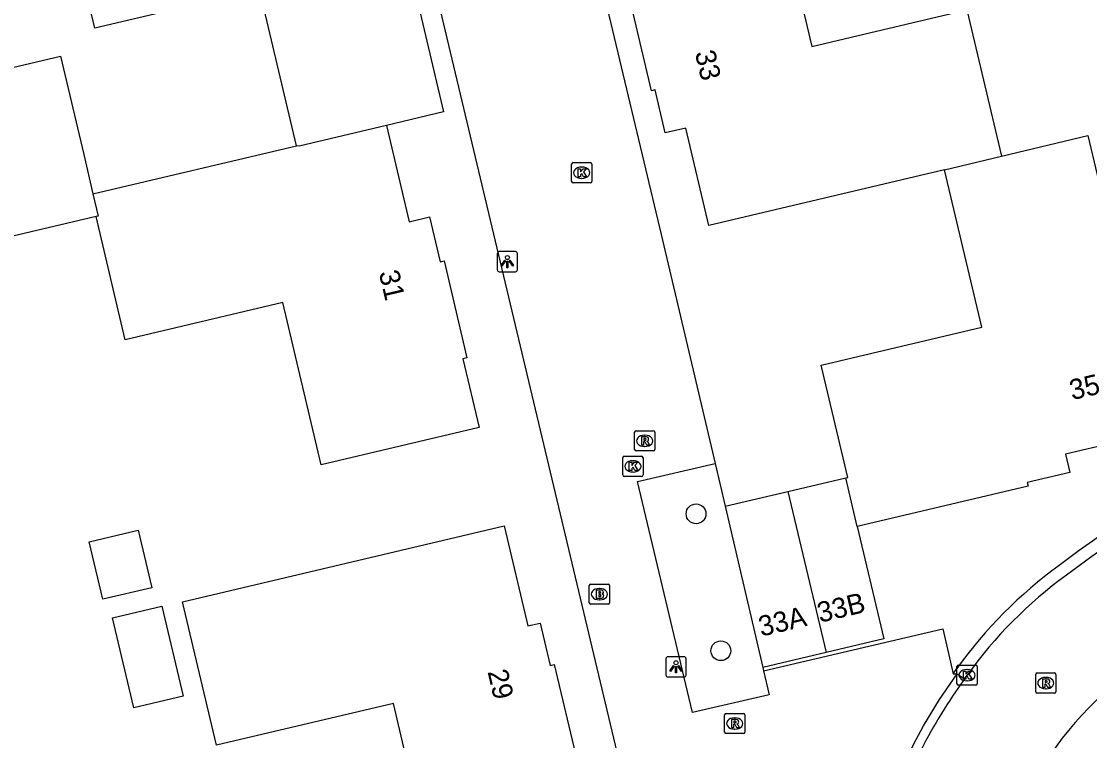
# Model space of a CAD drawing. Extents: x 157663 to 158496, y 379212 to 380934.
# Drawn here: x 158198.6 to 158251.4, y 380518.3 to 380553.9 of the extents above; entities that cross this region are included whole.
import ezdxf

# ---------------------------------------------------------------- set-up
doc = ezdxf.new("R2010")
doc.units = 0
for name, color, linetype in [('IMGEO_Boom', 7, 'Continuous'), ('IMGEO_Brandkraan', 7, 'Continuous'), ('IMGEO_Groenvoorziening', 7, 'Continuous'), ('IMGEO_Hek', 7, 'Continuous'), ('IMGEO_Kolk', 7, 'Continuous'), ('IMGEO_Lichtpunt', 7, 'Continuous'), ('IMGEO_Pand', 7, 'Continuous'), ('IMGEO_Pand_nummerreeks', 7, 'Continuous'), ('IMGEO_Rijbaan_lokaal_open', 7, 'Continuous'), ('IMGEO_Rioolput', 7, 'Continuous'), ('IMGEO_Voetpad_open', 7, 'Continuous')]:
    doc.layers.add(name, color=color, linetype=linetype)

msp = doc.modelspace()

# ---------------------------------------------------------------- linework, layer by layer
at = {"layer": 'IMGEO_Boom'}
for centre in [(158231.968, 380529.528), (158233.196, 380522.753)]:
    msp.add_circle(centre, 0.489, dxfattribs=at)
at = {"layer": 'IMGEO_Brandkraan'}
for p, q in [((158226.762, 380526.053), (158227.614, 380526.053)), ((158226.687, 380525.127), (158226.687, 380525.979)), ((158227.175, 380525.833), (158227.2, 380525.833)), ((158227.688, 380525.979), (158227.688, 380525.127)), ((158227.614, 380525.053), (158226.762, 380525.053)), ((158227.198, 380525.273), (158227.173, 380525.273))]:
    msp.add_line(p, q, dxfattribs=at)
for points in [[(158226.762, 380526.053), (158227.614, 380526.053)], [(158226.687, 380525.127), (158226.687, 380525.979)], [(158227.035, 380525.753), (158227.035, 380525.353), (158227.248, 380525.353)], [(158227.266, 380525.753), (158227.035, 380525.753)], [(158227.214, 380525.672), (158227.16, 380525.672), (158227.16, 380525.596)], [(158227.16, 380525.596), (158227.213, 380525.596)], [(158227.222, 380525.52), (158227.16, 380525.52), (158227.16, 380525.439)], [(158227.688, 380525.979), (158227.688, 380525.127)], [(158227.614, 380525.053), (158226.762, 380525.053)], [(158227.16, 380525.439), (158227.222, 380525.439)]]:
    msp.add_lwpolyline(points, dxfattribs=at)
for centre, radius, start, end in [((158226.764, 380525.977), 0.0765, 91.552, 178.448), ((158226.764, 380525.977), 0.0765, 91.552, 178.448), ((158227.612, 380525.977), 0.0765, 1.552, 88.448), ((158227.612, 380525.977), 0.0765, 1.552, 88.448), ((158227.215, 380525.634), 0.0379, 267.8285, 90.9355), ((158227.223, 380525.479), 0.0404, 269.8759, 90.5077), ((158227.27, 380525.608), 0.145, 59.4692, 91.5367), ((158227.295, 380525.655), 0.0922, 285.5137, 58.1501), ((158227.3, 380525.463), 0.105, 301.3115, 78.989), ((158226.764, 380525.129), 0.0765, 181.552, 268.448), ((158226.764, 380525.129), 0.0765, 181.552, 268.448), ((158227.254, 380525.604), 0.251, 268.6676, 293.5347), ((158227.612, 380525.129), 0.0765, 271.552, 358.448), ((158227.612, 380525.129), 0.0765, 271.552, 358.448)]:
    msp.add_arc(centre, radius, start, end, dxfattribs=at)
for centre, major_axis, ratio, start_param, end_param in [((158227.174, 380525.553), (-0.387, 0.002), 0.722429, 4.712389, 7.853982), ((158227.199, 380525.553), (-0.39, 0.002), 0.717154, 1.570796, 4.712389)]:
    msp.add_ellipse(centre, major_axis=major_axis, ratio=ratio, start_param=start_param, end_param=end_param, dxfattribs=at)
at = {"layer": 'IMGEO_Groenvoorziening'}
for points in [[(158232.907, 380532.013), (158233.403, 380529.904)], [(158235.273, 380521.928), (158235.314, 380521.754)]]:
    msp.add_lwpolyline(points, dxfattribs=at)
at = {"layer": 'IMGEO_Hek'}
for points in [[(158230.238, 380543.354), (158232.907, 380532.013)], [(158232.907, 380532.013), (158233.403, 380529.904)]]:
    msp.add_lwpolyline(points, dxfattribs=at)
at = {"layer": 'IMGEO_Kolk'}
for p, q in [((158225.811, 380545.977), (158225.811, 380546.829)), ((158225.886, 380546.903), (158226.738, 380546.903)), ((158226.299, 380546.683), (158226.324, 380546.683)), ((158226.812, 380546.829), (158226.812, 380545.977)), ((158226.322, 380546.123), (158226.297, 380546.123)), ((158226.738, 380545.903), (158225.886, 380545.903)), ((158228.419, 380532.377), (158229.271, 380532.377)), ((158228.344, 380531.451), (158228.344, 380532.303)), ((158228.832, 380532.157), (158228.857, 380532.157)), ((158229.345, 380532.303), (158229.345, 380531.451)), ((158229.271, 380531.377), (158228.419, 380531.377)), ((158228.855, 380531.597), (158228.83, 380531.597)), ((158244.88, 380521.121), (158244.88, 380521.973)), ((158244.955, 380522.047), (158245.807, 380522.047)), ((158245.368, 380521.827), (158245.393, 380521.827)), ((158245.881, 380521.973), (158245.881, 380521.121)), ((158245.391, 380521.267), (158245.366, 380521.267)), ((158245.807, 380521.047), (158244.955, 380521.047))]:
    msp.add_line(p, q, dxfattribs=at)
for points in [[(158225.811, 380545.977), (158225.811, 380546.829)], [(158225.886, 380546.903), (158226.738, 380546.903)], [(158226.812, 380546.829), (158226.812, 380545.977)], [(158226.132, 380546.603), (158226.255, 380546.603), (158226.255, 380546.452), (158226.385, 380546.603), (158226.549, 380546.603), (158226.403, 380546.452), (158226.556, 380546.203), (158226.404, 380546.203), (158226.319, 380546.367), (158226.255, 380546.3), (158226.255, 380546.203), (158226.132, 380546.203), (158226.132, 380546.603)], [(158226.738, 380545.903), (158225.886, 380545.903)], [(158228.419, 380532.377), (158229.271, 380532.377)], [(158228.344, 380531.451), (158228.344, 380532.303)], [(158228.665, 380532.077), (158228.788, 380532.077), (158228.788, 380531.926), (158228.918, 380532.077), (158229.082, 380532.077), (158228.936, 380531.926), (158229.089, 380531.677), (158228.937, 380531.677), (158228.852, 380531.841), (158228.788, 380531.774), (158228.788, 380531.677), (158228.665, 380531.677), (158228.665, 380532.077)], [(158229.345, 380532.303), (158229.345, 380531.451)], [(158229.271, 380531.377), (158228.419, 380531.377)], [(158244.88, 380521.121), (158244.88, 380521.973)], [(158244.955, 380522.047), (158245.807, 380522.047)], [(158245.881, 380521.973), (158245.881, 380521.121)], [(158245.201, 380521.747), (158245.324, 380521.747), (158245.324, 380521.596), (158245.454, 380521.747), (158245.618, 380521.747), (158245.472, 380521.596), (158245.625, 380521.347), (158245.473, 380521.347), (158245.388, 380521.511), (158245.324, 380521.444), (158245.324, 380521.347), (158245.201, 380521.347), (158245.201, 380521.747)], [(158245.807, 380521.047), (158244.955, 380521.047)]]:
    msp.add_lwpolyline(points, dxfattribs=at)
for centre, start, end in [((158225.888, 380546.827), 91.552, 178.448), ((158225.888, 380546.827), 91.552, 178.448), ((158226.736, 380546.827), 1.552, 88.448), ((158226.736, 380546.827), 1.552, 88.448), ((158225.888, 380545.979), 181.552, 268.448), ((158225.888, 380545.979), 181.552, 268.448), ((158226.736, 380545.979), 271.552, 358.448), ((158226.736, 380545.979), 271.552, 358.448), ((158228.421, 380532.301), 91.552, 178.448), ((158228.421, 380532.301), 91.552, 178.448), ((158229.269, 380532.301), 1.552, 88.448), ((158229.269, 380532.301), 1.552, 88.448), ((158228.421, 380531.453), 181.552, 268.448), ((158228.421, 380531.453), 181.552, 268.448), ((158229.269, 380531.453), 271.552, 358.448), ((158229.269, 380531.453), 271.552, 358.448), ((158244.957, 380521.971), 91.552, 178.448), ((158244.957, 380521.971), 91.552, 178.448), ((158245.805, 380521.971), 1.552, 88.448), ((158245.805, 380521.971), 1.552, 88.448), ((158244.957, 380521.123), 181.552, 268.448), ((158244.957, 380521.123), 181.552, 268.448), ((158245.805, 380521.123), 271.552, 358.448), ((158245.805, 380521.123), 271.552, 358.448)]:
    msp.add_arc(centre, 0.0765, start, end, dxfattribs=at)
for centre, major_axis, ratio, start_param, end_param in [((158226.298, 380546.403), (-0.387, 0.002), 0.722429, 4.712389, 7.853982), ((158226.323, 380546.403), (-0.39, 0.002), 0.717154, 1.570796, 4.712389), ((158228.831, 380531.877), (-0.387, 0.002), 0.722429, 4.712389, 7.853982), ((158228.856, 380531.877), (-0.39, 0.002), 0.717154, 1.570796, 4.712389), ((158245.367, 380521.547), (-0.387, 0.002), 0.722429, 4.712389, 7.853982), ((158245.392, 380521.547), (-0.39, 0.002), 0.717154, 1.570796, 4.712389)]:
    msp.add_ellipse(centre, major_axis=major_axis, ratio=ratio, start_param=start_param, end_param=end_param, dxfattribs=at)
at = {"layer": 'IMGEO_Lichtpunt'}
for p, q in [((158222.133, 380542.409), (158222.133, 380541.602)), ((158222.133, 380542.409), (158222.133, 380541.602)), ((158223.035, 380542.504), (158222.227, 380542.504)), ((158223.035, 380542.504), (158222.227, 380542.504)), ((158223.129, 380541.602), (158223.129, 380542.409)), ((158223.129, 380541.602), (158223.129, 380542.409)), ((158222.227, 380541.508), (158223.035, 380541.508)), ((158222.227, 380541.508), (158223.035, 380541.508)), ((158230.478, 380522.361), (158230.478, 380521.554)), ((158230.478, 380522.361), (158230.478, 380521.554)), ((158231.38, 380522.456), (158230.572, 380522.456)), ((158231.38, 380522.456), (158230.572, 380522.456)), ((158231.474, 380521.554), (158231.474, 380522.361)), ((158231.474, 380521.554), (158231.474, 380522.361)), ((158230.572, 380521.46), (158231.38, 380521.46)), ((158230.572, 380521.46), (158231.38, 380521.46))]:
    msp.add_line(p, q, dxfattribs=at)
for points in [[(158222.507, 380542.073), (158222.546, 380542.045), (158222.358, 380541.783), (158222.32, 380541.81), (158222.507, 380542.073)], [(158222.609, 380542.025), (158222.656, 380542.025), (158222.656, 380541.703), (158222.609, 380541.703), (158222.609, 380542.025)], [(158222.719, 380542.045), (158222.757, 380542.072), (158222.944, 380541.81), (158222.905, 380541.782), (158222.719, 380542.045)], [(158230.852, 380522.025), (158230.891, 380521.997), (158230.703, 380521.735), (158230.665, 380521.762), (158230.852, 380522.025)], [(158230.954, 380521.977), (158231.001, 380521.977), (158231.001, 380521.655), (158230.954, 380521.655), (158230.954, 380521.977)], [(158231.064, 380521.997), (158231.102, 380522.024), (158231.289, 380521.762), (158231.25, 380521.734), (158231.064, 380521.997)]]:
    msp.add_lwpolyline(points, dxfattribs=at)
for centre in [(158222.632, 380542.207), (158230.977, 380522.159)]:
    msp.add_circle(centre, 0.0994, dxfattribs=at)
for centre, start, end in [((158222.227, 380542.409), 90, 180), ((158222.227, 380542.409), 90, 180), ((158223.035, 380542.409), 0, 90), ((158223.035, 380542.409), 0, 90), ((158222.227, 380541.602), 180, 270), ((158222.227, 380541.602), 180, 270), ((158223.035, 380541.602), 270, 0), ((158223.035, 380541.602), 270, 360), ((158230.572, 380522.361), 90, 180), ((158230.572, 380522.361), 90, 180), ((158231.38, 380522.361), 0, 90), ((158231.38, 380522.361), 0, 90), ((158230.572, 380521.554), 180, 270), ((158230.572, 380521.554), 180, 270), ((158231.38, 380521.554), 270, 0), ((158231.38, 380521.554), 270, 360)]:
    msp.add_arc(centre, 0.0946, start, end, dxfattribs=at)
at = {"layer": 'IMGEO_Pand'}
for points in [[(158212.202, 380547.732), (158210.376, 380555.476), (158202.214, 380553.552), (158201.475, 380556.687), (158200.327, 380561.553), (158208.791, 380563.549), (158208.844, 380563.323), (158210.663, 380563.752), (158210.781, 380563.252), (158215.932, 380564.466), (158219.481, 380549.414), (158216.649, 380548.746)], [(158244.27, 380546.547), (158232.594, 380543.79), (158231.456, 380548.609), (158230.445, 380548.37), (158229.942, 380550.498), (158229.763, 380550.456), (158227.812, 380558.721), (158235.815, 380560.61), (158236.572, 380557.404), (158237.694, 380552.652), (158240.274, 380553.261), (158245.371, 380554.464), (158247.079, 380547.23)], [(158187.735, 380537.778), (158185.487, 380547.312), (158190.285, 380548.444), (158190.055, 380549.42), (158192.256, 380549.939), (158192.195, 380550.201), (158200.521, 380552.165), (158201.669, 380547.299), (158202.127, 380545.357)], [(158216.649, 380548.746), (158217.772, 380543.981), (158218.779, 380544.218), (158219.302, 380542), (158219.499, 380542.047), (158220.632, 380537.241), (158220.437, 380537.195), (158221.239, 380533.796), (158213.421, 380531.952), (158211.529, 380539.978), (158203.719, 380538.136), (158202.281, 380544.235)], [(158216.649, 380548.746), (158212.328, 380547.722), (158212.202, 380547.732)], [(158247.079, 380547.23), (158251.36, 380548.241), (158252.047, 380545.332), (158252.147, 380545.356)], [(158202.127, 380545.357), (158212.202, 380547.732)], [(158244.27, 380546.547), (158247.079, 380547.23)], [(158239.376, 380531.305), (158239.475, 380531.328), (158238.162, 380536.889), (158246.107, 380538.764), (158244.27, 380546.547)], [(158202.127, 380545.357), (158202.388, 380544.26), (158202.281, 380544.235)], [(158202.281, 380544.235), (158194.371, 380542.37), (158196.187, 380534.669), (158188.862, 380532.941)], [(158254.07, 380537.657), (158255.026, 380533.607), (158250.256, 380532.48), (158250.471, 380531.569), (158248.359, 380531.07), (158248.401, 380530.889), (158239.946, 380528.893)], [(158236.519, 380530.635), (158239.376, 380531.305)], [(158239.946, 380528.893), (158239.376, 380531.305)], [(158233.403, 380529.904), (158236.519, 380530.635)], [(158236.519, 380530.635), (158238.401, 380522.667)], [(158233.403, 380529.904), (158235.273, 380521.928)], [(158202.615, 380525.301), (158201.944, 380528.147), (158204.368, 380528.718), (158205.039, 380525.873), (158202.615, 380525.301)], [(158220.849, 380512.586), (158218.887, 380512.123), (158216.994, 380520.152), (158208.234, 380518.086), (158206.561, 380525.179), (158222.48, 380528.933), (158223.648, 380523.983), (158224.253, 380524.126), (158224.748, 380522.028), (158224.955, 380522.077), (158226.095, 380517.285), (158228.061, 380517.741)], [(158239.946, 380528.893), (158241.258, 380523.342), (158238.401, 380522.667)], [(158203.103, 380524.384), (158205.539, 380524.958), (158206.587, 380520.513), (158204.152, 380519.938), (158203.103, 380524.384)], [(158238.401, 380522.667), (158235.273, 380521.928)]]:
    msp.add_lwpolyline(points, dxfattribs=at)
at = {"layer": 'IMGEO_Rijbaan_lokaal_open'}
msp.add_lwpolyline([(158245.253, 380521.357), (158245.381, 380521.547)], dxfattribs=at)
for centre, radius, start, end in [((158289.386, 380474.223), 65.273, 121.30113, 126.79075), ((158263.464, 380508.509), 22.294, 126.211, 144.2073), ((158266.453, 380505.943), 26.211, 143.981, 152.9559), ((158263.673, 380507.946), 17.156, 127.2371, 154.1336)]:
    msp.add_arc(centre, radius, start, end, dxfattribs=at)
at = {"layer": 'IMGEO_Rioolput'}
for p, q in [((158228.928, 380532.712), (158228.928, 380533.564)), ((158229.003, 380533.638), (158229.855, 380533.638)), ((158229.416, 380533.418), (158229.441, 380533.418)), ((158229.929, 380533.564), (158229.929, 380532.712)), ((158229.855, 380532.638), (158229.003, 380532.638)), ((158229.439, 380532.858), (158229.414, 380532.858)), ((158248.775, 380520.728), (158248.775, 380521.58)), ((158248.85, 380521.654), (158249.702, 380521.654)), ((158249.263, 380521.434), (158249.288, 380521.434)), ((158249.776, 380521.58), (158249.776, 380520.728)), ((158249.286, 380520.874), (158249.261, 380520.874)), ((158249.702, 380520.654), (158248.85, 380520.654)), ((158233.384, 380518.729), (158233.384, 380519.581)), ((158233.459, 380519.655), (158234.311, 380519.655)), ((158233.872, 380519.435), (158233.897, 380519.435)), ((158234.385, 380519.581), (158234.385, 380518.729)), ((158234.311, 380518.655), (158233.459, 380518.655)), ((158233.895, 380518.875), (158233.87, 380518.875))]:
    msp.add_line(p, q, dxfattribs=at)
for points in [[(158228.928, 380532.712), (158228.928, 380533.564)], [(158229.003, 380533.638), (158229.855, 380533.638)], [(158229.929, 380533.564), (158229.929, 380532.712)], [(158229.517, 380533.336), (158229.265, 380533.338), (158229.265, 380532.938)], [(158229.265, 380532.938), (158229.389, 380532.938), (158229.389, 380533.1), (158229.4, 380533.1)], [(158229.443, 380533.257), (158229.389, 380533.257), (158229.389, 380533.176)], [(158229.389, 380533.176), (158229.441, 380533.176)], [(158229.447, 380533.071), (158229.518, 380532.938), (158229.658, 380532.938), (158229.593, 380533.064)], [(158229.855, 380532.638), (158229.003, 380532.638)], [(158248.775, 380520.728), (158248.775, 380521.58)], [(158248.85, 380521.654), (158249.702, 380521.654)], [(158249.364, 380521.352), (158249.112, 380521.354), (158249.112, 380520.954)], [(158249.29, 380521.273), (158249.236, 380521.273), (158249.236, 380521.192)], [(158249.776, 380521.58), (158249.776, 380520.728)], [(158249.112, 380520.954), (158249.236, 380520.954), (158249.236, 380521.116), (158249.247, 380521.116)], [(158249.236, 380521.192), (158249.288, 380521.192)], [(158249.294, 380521.087), (158249.365, 380520.954), (158249.505, 380520.954), (158249.44, 380521.08)], [(158249.702, 380520.654), (158248.85, 380520.654)], [(158233.384, 380518.729), (158233.384, 380519.581)], [(158233.459, 380519.655), (158234.311, 380519.655)], [(158233.973, 380519.353), (158233.721, 380519.355), (158233.721, 380518.955)], [(158233.899, 380519.274), (158233.845, 380519.274), (158233.845, 380519.193)], [(158233.845, 380519.193), (158233.897, 380519.193)], [(158234.385, 380519.581), (158234.385, 380518.729)], [(158234.311, 380518.655), (158233.459, 380518.655)], [(158233.721, 380518.955), (158233.845, 380518.955), (158233.845, 380519.117), (158233.856, 380519.117)], [(158233.903, 380519.088), (158233.974, 380518.955), (158234.114, 380518.955), (158234.049, 380519.081)]]:
    msp.add_lwpolyline(points, dxfattribs=at)
for centre, radius, start, end in [((158229.005, 380533.562), 0.0765, 91.552, 178.448), ((158229.005, 380533.562), 0.0765, 91.552, 178.448), ((158229.853, 380533.562), 0.0765, 1.552, 88.448), ((158229.853, 380533.562), 0.0765, 1.552, 88.448), ((158229.399, 380533.047), 0.0533, 26.0293, 88.6989), ((158229.425, 380533.365), 0.19, 274.7715, 282.9687), ((158229.449, 380533.161), 0.0964, 77.0061, 93.1865), ((158229.463, 380533.218), 0.0378, 276.6634, 79.6772), ((158229.516, 380533.226), 0.109, 350.3612, 89.416), ((158229.514, 380533.226), 0.112, 277.5842, 350.9817), ((158229.498, 380533.011), 0.108, 29.5134, 73.7905), ((158229.005, 380532.714), 0.0765, 181.552, 268.448), ((158229.005, 380532.714), 0.0765, 181.552, 268.448), ((158229.853, 380532.714), 0.0765, 271.552, 358.448), ((158229.853, 380532.714), 0.0765, 271.552, 358.448), ((158248.852, 380521.578), 0.0765, 91.552, 178.448), ((158248.852, 380521.578), 0.0765, 91.552, 178.448), ((158249.296, 380521.177), 0.0964, 77.0061, 93.1865), ((158249.31, 380521.234), 0.0378, 276.6634, 79.6772), ((158249.363, 380521.242), 0.109, 350.3612, 89.416), ((158249.7, 380521.578), 0.0765, 1.552, 88.448), ((158249.7, 380521.578), 0.0765, 1.552, 88.448), ((158249.246, 380521.063), 0.0533, 26.0293, 88.6989), ((158249.272, 380521.381), 0.19, 274.7715, 282.9687), ((158249.361, 380521.242), 0.112, 277.5842, 350.9817), ((158249.345, 380521.027), 0.108, 29.5134, 73.7905), ((158248.852, 380520.73), 0.0765, 181.552, 268.448), ((158248.852, 380520.73), 0.0765, 181.552, 268.448), ((158249.7, 380520.73), 0.0765, 271.552, 358.448), ((158249.7, 380520.73), 0.0765, 271.552, 358.448), ((158233.461, 380519.579), 0.0765, 91.552, 178.448), ((158233.461, 380519.579), 0.0765, 91.552, 178.448), ((158233.881, 380519.382), 0.19, 274.7715, 282.9687), ((158233.905, 380519.178), 0.0964, 77.0061, 93.1865), ((158233.919, 380519.235), 0.0378, 276.6634, 79.6772), ((158233.972, 380519.243), 0.109, 350.3612, 89.416), ((158233.97, 380519.243), 0.112, 277.5842, 350.9817), ((158234.309, 380519.579), 0.0765, 1.552, 88.448), ((158234.309, 380519.579), 0.0765, 1.552, 88.448), ((158233.461, 380518.731), 0.0765, 181.552, 268.448), ((158233.461, 380518.731), 0.0765, 181.552, 268.448), ((158233.855, 380519.064), 0.0533, 26.0293, 88.6989), ((158233.954, 380519.028), 0.108, 29.5134, 73.7905), ((158234.309, 380518.731), 0.0765, 271.552, 358.448), ((158234.309, 380518.731), 0.0765, 271.552, 358.448)]:
    msp.add_arc(centre, radius, start, end, dxfattribs=at)
for centre, major_axis, ratio, start_param, end_param in [((158229.415, 380533.138), (-0.387, 0.002), 0.722429, 4.712389, 7.853982), ((158229.44, 380533.138), (-0.39, 0.002), 0.717154, 1.570796, 4.712389), ((158249.262, 380521.154), (-0.387, 0.002), 0.722429, 4.712389, 7.853982), ((158249.287, 380521.154), (-0.39, 0.002), 0.717154, 1.570796, 4.712389), ((158233.871, 380519.155), (-0.387, 0.002), 0.722429, 4.712389, 7.853982), ((158233.896, 380519.155), (-0.39, 0.002), 0.717154, 1.570796, 4.712389)]:
    msp.add_ellipse(centre, major_axis=major_axis, ratio=ratio, start_param=start_param, end_param=end_param, dxfattribs=at)
at = {"layer": 'IMGEO_Voetpad_open'}
for points in [[(158226.289, 380559.958), (158230.238, 380543.354), (158232.907, 380532.013)], [(158228.061, 380517.741), (158218.496, 380557.919)], [(158235.314, 380521.754), (158235.594, 380520.58), (158231.797, 380519.705), (158229.076, 380531.128), (158232.907, 380532.013)], [(158235.314, 380521.754), (158244.18, 380523.842), (158244.692, 380521.61)], [(158244.692, 380521.61), (158244.875, 380521.874)], [(158239.414, 380511.303), (158239.674, 380511.491), (158242.512, 380517.683), (158242.859, 380518.366), (158243.226, 380519.039), (158244.019, 380520.35), (158244.887, 380521.613)], [(158244.692, 380521.61), (158244.887, 380521.613)], [(158244.887, 380521.613), (158245.253, 380521.357)]]:
    msp.add_lwpolyline(points, dxfattribs=at)
for centre, radius, start, end in [((158286.159, 380478.944), 60.163, 120.78637, 127.02118), ((158263.238, 380508.736), 22.579, 126.1016, 144.417)]:
    msp.add_arc(centre, radius, start, end, dxfattribs=at)

# ---------------------------------------------------------------- texts
at = {"layer": 'IMGEO_Pand_nummerreeks'}
for s, rotation, p in [('33', 283.2819, (158231.907, 380552.341)), ('31', 283.2651, (158216.268, 380541.462)), ('35', 13.2926, (158250.578, 380535.147)), ('33B', 13.2926, (158238.1, 380524.137)), ('33A', 13.2926, (158235.192, 380523.45)), ('29', 283.2738, (158221.647, 380521.72))]:
    msp.add_text(s, height=1, rotation=rotation, dxfattribs=at).set_placement(p)

doc.saveas('drawing.dxf')
